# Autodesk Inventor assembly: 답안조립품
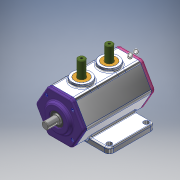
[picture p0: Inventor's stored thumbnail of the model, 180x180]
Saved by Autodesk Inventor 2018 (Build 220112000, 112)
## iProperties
Created: 2021-06
Part Number: 답안조립품
Document SubType Name: Assembly
Designer: 1class19
Author: 1class19
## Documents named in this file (11)
- C:\Users\1class19\Desktop\710606V1042\답안조립품.iam
- C:\Users\1class19\Desktop\710606V1042\부품1.ipt
- C:\Users\1class19\Desktop\710606V1042\편심축.ipt
- C:\Users\1class19\Desktop\710606V1042\슬라이더.ipt
- C:\Users\1class19\Desktop\710606V1042\부시.ipt
- C:\Users\1class19\Desktop\710606V1042\베어링 6203.ipt
- C:\Users\1class19\Desktop\710606V1042\베어링 6302.ipt
- C:\Users\1class19\Desktop\710606V1042\오일실.ipt
- C:\Users\1class19\Desktop\710606V1042\앞커버.ipt
- C:\Users\1class19\Desktop\710606V1042\뒷커버.ipt
- C:\Users\1class19\Desktop\710606V1042\볼트 M4.ipt
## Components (10 placed, 3 different names)
1. 7-베어링 6203:1
2. 8-오일실:1
3. 9-M4-소켓머리:1
4. 9-M4-소켓머리:2
5. 9-M4-소켓머리:3
6. 9-M4-소켓머리:4
7. 9-M4-소켓머리:5
8. 9-M4-소켓머리:6
9. 9-M4-소켓머리:7
10. 9-M4-소켓머리:8
